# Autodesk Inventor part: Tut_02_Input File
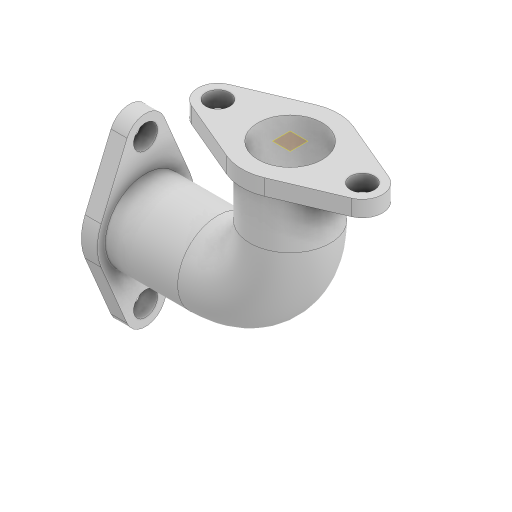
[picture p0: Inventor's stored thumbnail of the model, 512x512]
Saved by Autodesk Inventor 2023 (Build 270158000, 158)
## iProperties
Created: 2022-08
Part Number: Tut_02_Input File
Material: Generic
Document SubType Name: Modeling
Designer: LENOVO-CADCIM
Density: 1 g/cm^3
Appearance: Default
Author: LENOVO-CADCIM
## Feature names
1. Sweep1
2. Shell2
3. Extrusion1
4. Extrusion2
5. Extrusion3
6. Extrusion4
7. Extrusion5
## Parameters: d0 = 175 mm, d4 = 0, d5 = 0, d16 = 0, d20 = 0, d26 = 0, d29 = 149.75 mm, d30 = 0, d31 = 221.75 mm, d32 = 0
